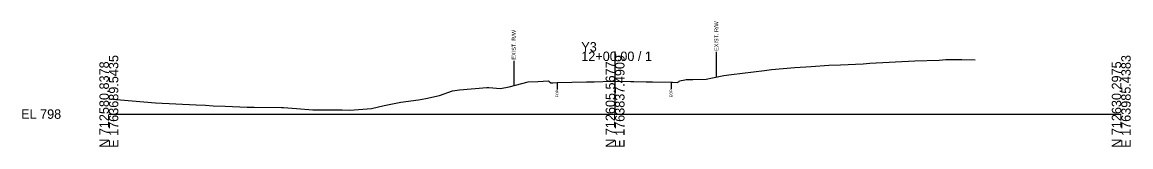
# Model space of a CAD drawing. Extents: x -26 to 2903, y -10 to 5022.
# Drawn here: x -25.7 to 302.8, y 1990.3 to 2027.2 of the extents above; entities that cross this region are included whole.
import ezdxf

# ---------------------------------------------------------------- set-up
doc = ezdxf.new("R2010")
doc.units = 0
for name, color, linetype in [('Default', 7, 'Continuous'), ('Exist Cross Section Cell', 7, 'Continuous'), ('Exist XS Ground Line', 7, 'Continuous'), ('Old_Level_10', 7, 'Continuous')]:
    doc.layers.add(name, color=color, linetype=linetype)

msp = doc.modelspace()

# ---------------------------------------------------------------- linework, layer by layer
at = {"layer": 'Exist Cross Section Cell'}
for p, q in [((150, 2000), (150, 2018.51)), ((0, 2000), (150, 2000)), ((150, 2000), (300, 2000))]:
    msp.add_line(p, q, dxfattribs=at)
at = {"layer": 'Exist XS Ground Line'}
msp.add_lwpolyline([(0, 2004.52), (13.86, 2003.32), (25.86, 2002.74), (28.59, 2002.61), (30.88, 2002.43), (34.42, 2002.32), (41.02, 2002.01), (43.1, 2002.05), (51.16, 2001.99), (51.79, 2001.94), (55.57, 2001.63), (60.48, 2001.22), (61.3, 2001.26), (69.16, 2001.28), (71.43, 2001.17), (77.85, 2001.64), (81.57, 2002.53), (86.54, 2003.52), (91.71, 2004.25), (93.97, 2004.59), (98, 2005.48), (101.85, 2006.84), (103.91, 2007.16), (111.99, 2007.85), (112.57, 2007.83), (116.05, 2007.57), (118.6, 2008.04), (124.23, 2009.55), (127.13, 2009.61), (130.31, 2009.82), (130.52, 2009.66), (130.92, 2009.21), (131.55, 2009.26), (132.83, 2009.37), (141.54, 2009.52), (143.76, 2009.57), (149, 2009.7), (150, 2009.72), (150.06, 2009.72), (154.68, 2009.64), (155.57, 2009.62), (159.25, 2009.57), (161.08, 2009.54), (166.59, 2009.46), (167.02, 2009.41), (168.43, 2009.32), (168.96, 2009.67), (169.12, 2009.82), (170.67, 2010.18), (171.08, 2010.24), (173.02, 2010.26), (177.02, 2010.33), (178.86, 2010.78), (182.2, 2011.43), (182.25, 2011.43), (184.48, 2011.68), (194.26, 2012.92), (196.35, 2013.2), (203.24, 2013.83), (208.15, 2014.04), (213.38, 2014.5), (216.84, 2014.63), (223.52, 2014.91), (225.52, 2015.06), (238.81, 2015.73), (246.02, 2015.93), (248.01, 2016.13), (252.8, 2016.21), (256.68, 2016.08)], dxfattribs=at)
at = {"layer": 'Old_Level_10'}
for p, q in [((180, 2018.4), (180, 2011)), ((120, 2015.81), (120, 2008.41)), ((132.83, 2009.37), (132.83, 2007.32)), ((166.59, 2009.46), (166.59, 2007.41))]:
    msp.add_line(p, q, dxfattribs=at)

# ---------------------------------------------------------------- texts
at = {"layer": 'Default'}
msp.add_text('-', height=0.0001, dxfattribs=at).set_placement((0, 2000))
at = {"layer": 'Exist Cross Section Cell'}
for s, p in [('Y3', (140, 2018.51)), ('12+00.00 / 1', (140, 2015.71)), ('EL 798', (-26, 1998.6))]:
    msp.add_text(s, height=2.8, dxfattribs=at).set_placement(p)
for s, p in [('E 1763689.5435', (2.8, 1990)), ('E 1763837.4909', (152.8, 1990)), ('E 1763985.4383', (302.8, 1990)), ('N 712580.8378', (0, 1990)), ('N 712605.5677', (150, 1990)), ('N 712630.2975', (300, 1990))]:
    msp.add_text(s, height=2.8, rotation=90, dxfattribs=at).set_placement(p)
at = {"layer": 'Old_Level_10'}
for s, height, p in [('EXIST. R/W', 1.181, (180.59, 2018.7)), ('EXIST. R/W', 1.181, (120.59, 2016.12)), ('EOP', 0.787, (133.23, 2004.92)), ('EOP', 0.787, (166.99, 2005.01))]:
    msp.add_text(s, height=height, rotation=90, dxfattribs=at).set_placement(p)

doc.saveas('drawing.dxf')
